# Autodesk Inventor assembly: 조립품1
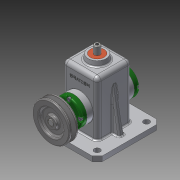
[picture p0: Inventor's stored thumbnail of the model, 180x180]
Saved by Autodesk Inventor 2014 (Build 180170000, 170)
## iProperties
Created: 2016-02
Part Number: 조립품1
Document SubType Name: Assembly
Designer: 703-05
Author: 703-05
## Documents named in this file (16)
- C:\Users\703-05\Desktop\460212V1015\조립품1.iam
- C:\Users\703-05\Desktop\460212V1015\본체.ipt
- C:\Users\703-05\Desktop\460212V1015\V벨트풀리.ipt
- C:\Users\703-05\Desktop\460212V1015\고정핀 1.2 x 10.ipt
- C:\Users\703-05\Desktop\460212V1015\뒤커버.ipt
- C:\Users\703-05\Desktop\460212V1015\링크.ipt
- C:\Users\703-05\Desktop\460212V1015\멈춤나사 M3x8.ipt
- C:\Users\703-05\Desktop\460212V1015\베어링 12 x 32 x 10.ipt
- C:\Users\703-05\Desktop\460212V1015\볼트 M4 x 12.ipt
- C:\Users\703-05\Desktop\460212V1015\부시.ipt
- C:\Users\703-05\Desktop\460212V1015\슬라이드.ipt
- C:\Users\703-05\Desktop\460212V1015\앞커버.ipt
- C:\Users\703-05\Desktop\460212V1015\오일실 12 25 7.ipt
- C:\Users\703-05\Desktop\460212V1015\키 4 x 4 x 10.ipt
- C:\Users\703-05\Desktop\460212V1015\편심축.ipt
- C:\Users\703-05\Desktop\460212V1015\핀 5 x 18.ipt
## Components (11 placed, 4 different names)
1. V벨트풀리:1
2. 고정핀 1.2 x 10:1
3. 핀 5 x 18:1
4. ISO 4762 M4 x 12:1
5. ISO 4762 M4 x 12:2
6. ISO 4762 M4 x 12:3
7. ISO 4762 M4 x 12:4
8. ISO 4762 M4 x 12:5
9. ISO 4762 M4 x 12:6
10. ISO 4762 M4 x 12:7
11. ISO 4762 M4 x 12:8
